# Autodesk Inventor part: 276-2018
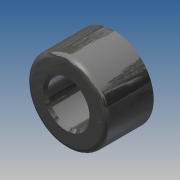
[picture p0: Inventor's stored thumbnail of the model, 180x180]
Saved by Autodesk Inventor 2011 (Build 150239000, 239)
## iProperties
Company: Autodesk Inc.
Created: 2010-06
Part Number: 276-2018
Document SubType Name: Modeling
Designer: Autodesk Inc.
Density: 1 g/cm^3
Catalog Web Link: http://www.vexrobotics.com/spacers.html
Description: A spacer is used to create a space between two objects, often to properly position them.
Vendor: Innovation First, Inc.
Author: Autodesk Inc.
Title: VEX Robotics Kit of Parts
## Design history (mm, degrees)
sketch "Sketch1"
  geometry: C1 r 4.064 at (0, 0); 1 further point
  constraints: 1 centre point, 1 coincident
  dimensions: "d0" = 8.128 diameter of C1
extrude "Extrusion1" new body sketch "Sketch1" distance "d1" = 4.826; taper "d2" = 0 deg
sketch "Sketch2"
  geometry: C1 r 4.064 at (0, 0) reference
hole "Hole1" sketch "Sketch2" at (0, 0) diameter "d3" = 4.2418; stored, may be unused: countersink angle "d7" = 82 deg, drill point angle "d9" = 118 deg; dims "d4" = 19.05, "d5" = 9.525, "d6" = 6.35, "d8" = 25.4
fillet "Fillet1" dims "d10" = 0.508
chamfer "Chamfer1" distance "d11" = 0.254; stored, may be unused: second distance "d12" = 3.175, angle "d13" = 45 deg
body "Solid1"
